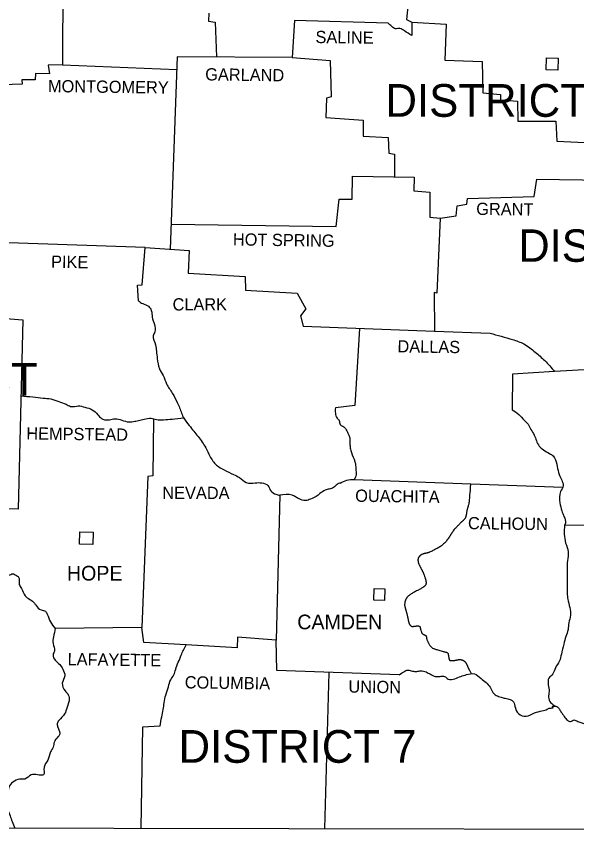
# Model space of a CAD drawing. Extents: x -819161 to 80911, y -6604 to 768454.
# Drawn here: x 80437.8 to 80589.5, y -4334.9 to -4115 of the extents above; entities that cross this region are included whole.
import ezdxf

# ---------------------------------------------------------------- set-up
doc = ezdxf.new("R2010")
doc.units = 0
doc.layers.add('SHET_Annotations', color=7, linetype='Continuous')

msp = doc.modelspace()

# ---------------------------------------------------------------- linework, layer by layer
at = {"layer": 'SHET_Annotations'}
for points in [[(80492.66, -4061.86), (80492.3, -4073.01), (80474.67, -4073.1), (80472.33, -4075.08), (80470.97, -4078.17), (80469.07, -4078.08), (80468.98, -4079.8), (80466.73, -4080.06), (80466.82, -4081.65), (80455.58, -4081.39), (80455.14, -4082.62), (80450.51, -4082.8), (80450.38, -4128.16), (80446.45, -4128.25), (80446.81, -4130.54), (80443.06, -4130.5), (80442.97, -4132.22), (80439.31, -4132.22), (80439.4, -4133.41), (80434.02, -4133.59), (80433.89, -4138.3), (80428.64, -4137.82), (80427.76, -4176)], [(80569.37, -4105.06), (80563.82, -4104.4), (80564.04, -4106.52), (80553.85, -4106.91), (80553.54, -4109.91), (80543.98, -4110.44), (80543.45, -4115.91), (80544.86, -4116.61), (80544.86, -4120.18)], [(80489.97, -4114.19), (80489.84, -4116.3), (80491.64, -4116.61), (80491.97, -4126.02)], [(80538.46, -4116.92), (80513.16, -4116.17), (80512.45, -4126.14), (80481.37, -4125.96), (80479.46, -4178.02)], [(80544.86, -4116.62), (80554.12, -4117.19), (80553.76, -4126.89), (80563.9, -4127.28), (80564.12, -4135.75), (80568.89, -4136.14), (80568.89, -4137.6), (80573.43, -4137.95), (80573.56, -4143.37), (80583.79, -4143.37), (80584.14, -4148.75), (80593.57, -4149.19), (80593.53, -4159.28)], [(80512.45, -4126.14), (80522.73, -4127.02), (80523.03, -4136.81), (80521.76, -4137.2), (80521.58, -4142.4), (80531.72, -4143.15), (80531.72, -4147.43), (80538.46, -4147.78), (80538.6, -4152.02), (80540.18, -4152.28), (80540.14, -4158.43)], [(80450.38, -4128.16), (80481.25, -4129.37)], [(80479.71, -4171.19), (80524.36, -4171.86), (80525.19, -4164.45), (80528.72, -4164.49), (80528.81, -4158.28), (80545.52, -4158.5), (80545.43, -4162.24), (80549.75, -4162.55), (80549.71, -4169.34), (80552.53, -4169.61)], [(80552.53, -4169.61), (80556.85, -4168.95), (80557.16, -4166.3), (80559.72, -4165.86), (80559.89, -4164.32), (80577.97, -4163.74), (80578.67, -4159.07), (80597.19, -4159.33)], [(80552.53, -4169.61), (80551.6, -4189.89), (80550.94, -4189.67), (80550.99, -4200.14)], [(80472.73, -4177.54), (80427.76, -4176), (80397.91, -4175.96), (80397.25, -4184.82), (80398.31, -4185.57), (80398.26, -4195.53), (80375.89, -4194.51)], [(80427.76, -4176), (80427.76, -4186.32), (80429.48, -4186.62), (80429.3, -4196.24), (80439.62, -4197.07), (80438.34, -4248.3), (80417.27, -4247.82)], [(80470.88, -4191.96), (80470.66, -4187.68), (80471.94, -4187.59), (80472.73, -4177.54), (80484.63, -4178.38), (80484.37, -4184.51), (80499.76, -4185.35), (80499.89, -4189.05), (80513.82, -4189.89), (80516.2, -4194.08), (80514.75, -4195.97), (80515.45, -4198.84), (80550.99, -4200.14)], [(80530.72, -4199.4), (80529.47, -4220.26), (80524.18, -4220.88)], [(80550.99, -4200.14), (80566.02, -4200.69)], [(80583.48, -4211.07), (80572.1, -4211.76), (80572.02, -4221.45)], [(80594.77, -4210.39), (80583.48, -4211.07)], [(80474.98, -4223.84), (80474.8, -4239.22), (80473.39, -4239.4), (80471.85, -4280.27)], [(80529.28, -4240.21), (80560.86, -4241.38), (80585.73, -4242.35)], [(80509.15, -4244.51), (80508.13, -4283.66), (80497.68, -4282.91), (80497.59, -4285.78), (80483.81, -4284.98)], [(80586.17, -4252.58), (80621.26, -4252.49)], [(80416.6, -4271.67), (80416.78, -4334.45), (80701.11, -4334.94)], [(80483.81, -4284.98), (80472.38, -4284.32), (80471.85, -4280.27), (80448.35, -4280.49)], [(80541.42, -4293.1), (80508.35, -4291.86), (80508.13, -4283.66)], [(80522.42, -4292.39), (80521.24, -4334.63)], [(80476.79, -4306.9), (80472.02, -4307.21), (80471.51, -4334.55)]]:
    msp.add_lwpolyline(points, dxfattribs=at)
for points in [[(80581.23, -4129.49), (80581.32, -4126.27), (80584.45, -4126.36), (80584.36, -4129.57)], [(80454.96, -4257.74), (80455.05, -4254.43), (80458.62, -4254.52), (80458.53, -4257.83)], [(80534.58, -4272.91), (80534.67, -4269.69), (80537.54, -4269.78), (80537.45, -4272.99)]]:
    msp.add_lwpolyline(points, close=True, dxfattribs=at)
for points in [[(80544.86, -4120.18), (80542.87, -4118.99), (80541.64, -4118.33), (80540.45, -4118.38), (80539.43, -4117.76), (80538.46, -4116.92)], [(80470.88, -4191.96), (80472.07, -4192.71), (80473.57, -4193.41), (80474.36, -4194.56), (80474.62, -4196.37), (80475.2, -4198.31), (80475.33, -4200.29), (80474.89, -4201.39), (80475.51, -4203.86), (80475.73, -4205.58), (80475.99, -4207.57), (80476.56, -4210.3), (80477.58, -4212.15), (80478.5, -4214.4), (80480.05, -4216.87), (80481.41, -4219.47), (80482.03, -4220.84), (80483.18, -4223.7), (80484.63, -4225.69), (80487.01, -4228.64), (80489.09, -4231.68), (80490.23, -4233.93), (80492.04, -4236.4), (80494.07, -4237.63), (80496.62, -4238.91), (80498.26, -4239.75), (80500.06, -4241.07), (80502.49, -4241.16), (80504.25, -4241.16), (80505.93, -4241.91), (80506.68, -4243.28), (80508.09, -4244.25), (80509.15, -4244.51)], [(80566.02, -4200.69), (80572.1, -4202.41), (80575.19, -4203.6), (80578.28, -4205.85), (80580.83, -4208.1), (80583.48, -4211.07)], [(80439.1, -4217.67), (80442.35, -4217.93), (80445.09, -4218.24), (80447.16, -4218.46), (80449.32, -4219.21), (80451.3, -4219.91), (80452.54, -4220.48), (80454.61, -4220.35), (80456.42, -4220.7), (80458.4, -4221.41), (80459.9, -4222.73), (80460.87, -4223.75), (80462.63, -4224.14), (80464.13, -4223.88), (80465.9, -4224.06), (80467.88, -4224.63), (80469.55, -4224.58), (80470.88, -4224.28), (80472.42, -4223.92), (80474.32, -4223.7), (80475.77, -4224.06), (80477.71, -4224.1), (80480, -4223.92), (80483.11, -4223.58)], [(80524.18, -4220.88), (80524.18, -4222.34), (80524.66, -4223.7), (80525.19, -4224.32), (80525.46, -4225.38), (80526.16, -4225.82), (80527.13, -4226.79), (80527.71, -4228.07), (80528.06, -4228.95), (80528.1, -4230.05), (80528.15, -4231.11), (80528.32, -4232.39), (80529.25, -4234.77), (80529.51, -4235.69), (80529.65, -4236.49), (80529.74, -4237.81), (80529.69, -4239.35), (80529.28, -4240.21)], [(80572.02, -4221.45), (80573.78, -4222.64), (80575.23, -4224.23), (80576.34, -4225.33), (80577.09, -4226.7), (80577.97, -4228.24), (80579.33, -4231.2), (80580.48, -4232.21), (80582.11, -4233.23), (80583.08, -4233.89), (80584.1, -4236.14), (80584.58, -4238.38), (80585.42, -4240.41), (80585.82, -4241.96), (80585.11, -4243.5), (80584.93, -4246.58), (80585.46, -4248.75), (80586.04, -4250.24), (80586.43, -4252.05), (80586.17, -4252.58)], [(80525.46, -4241.2), (80524.66, -4241.56), (80523.69, -4242.4), (80522.5, -4242.84), (80521.45, -4243.15), (80519.99, -4244.07), (80518.98, -4244.87), (80517.48, -4245.53), (80516.07, -4245.97), (80514.35, -4245.48), (80513.42, -4244.95), (80512.45, -4244.51), (80509.15, -4244.51)], [(80525.46, -4241.2), (80527.27, -4240.46), (80529.28, -4240.21)], [(80586.17, -4252.58), (80586.48, -4257.43), (80587.18, -4259.77), (80587.01, -4262.19), (80586.87, -4264.62), (80586.92, -4266.78), (80586.87, -4268.89), (80586.92, -4271.05), (80587.05, -4272.6), (80587.62, -4274.85), (80587.8, -4276.96), (80587.36, -4278.99), (80587.14, -4280.84), (80586.52, -4282.69), (80585.99, -4284.77), (80585.33, -4287.5), (80584.8, -4289.31), (80583.7, -4291.16), (80582.99, -4292.83), (80581.94, -4293.94), (80581.8, -4295.79), (80582.02, -4297.55), (80581.85, -4299.09), (80582.42, -4300.55), (80583.79, -4301.56)], [(80416.6, -4271.67), (80419.29, -4270.52), (80420.53, -4270.88), (80421.5, -4271.89), (80422.69, -4271.94), (80423.31, -4271.01), (80424.45, -4270.88), (80425.38, -4270.97), (80426.39, -4270.39), (80427.23, -4270), (80428.38, -4269.6), (80429.26, -4269.25), (80430.01, -4268.41), (80431.46, -4267.75), (80433.05, -4267.17), (80433.49, -4266.38), (80434.28, -4266.07), (80435.83, -4266.16), (80436.89, -4265.72), (80437.72, -4266.12), (80438.47, -4266.64), (80438.65, -4268.63), (80439.27, -4269.73), (80440.24, -4271.67), (80441.51, -4272.69), (80442.75, -4273.7), (80443.19, -4274.32), (80444.56, -4275.51), (80445.7, -4275.86), (80446.23, -4276.7), (80447.07, -4278.77), (80448.35, -4280.49)], [(80448.35, -4280.49), (80447.91, -4282.78), (80447.78, -4284.59), (80448.17, -4286.62), (80447.78, -4287.68), (80448.39, -4289.13), (80449.58, -4290.28), (80450.42, -4291.51), (80450.95, -4293.36), (80450.29, -4295.35), (80451.04, -4297.42), (80451.74, -4298.21), (80452.18, -4299.49), (80451.57, -4301.83), (80450.91, -4303.63), (80449.36, -4305.4), (80448.92, -4306.28), (80449.14, -4307.43), (80449.54, -4309.28), (80449.1, -4309.85), (80448.13, -4311.17), (80447.78, -4312.63), (80447.07, -4313.91), (80446.36, -4316.11), (80445.35, -4318.01), (80445.17, -4320.12), (80443.59, -4320.08), (80441.87, -4320.12), (80440.19, -4321.23), (80438.74, -4321.31), (80436.93, -4322.06), (80435.83, -4323.52), (80435.47, -4325.15), (80434.99, -4326.69), (80435.43, -4329.34), (80436.14, -4331.19), (80436.71, -4332.69), (80437.45, -4334.49)], [(80476.79, -4306.9), (80477.18, -4304.43), (80477.58, -4302.44), (80477.84, -4300.64), (80478.28, -4298.52), (80478.99, -4296.27), (80479.61, -4294.42), (80480.44, -4293.1), (80480.97, -4291.55), (80481.68, -4289.66), (80482.43, -4287.76), (80483.81, -4284.98)], [(80541.42, -4293.1), (80542.7, -4292.22), (80543.84, -4291.78), (80545.03, -4292.04), (80546.22, -4292.13), (80547.33, -4292), (80548.74, -4292.26), (80549.88, -4292.92), (80551.21, -4293.49), (80552.53, -4293.49), (80553.67, -4293.49), (80554.73, -4294.2), (80556.54, -4294.11), (80558.13, -4293.49), (80559.67, -4293.01), (80561.79, -4292.79), (80563.59, -4294.07), (80564.96, -4295.17), (80566.02, -4296.4), (80566.81, -4297.82), (80567.7, -4298.61), (80569.06, -4299.14), (80570.16, -4299.4), (80571.44, -4299.76), (80572.15, -4300.11), (80572.77, -4301.52), (80573.78, -4303.59), (80575.76, -4304.25), (80578.1, -4303.33), (80580.08, -4302.8), (80581.49, -4302.36), (80582.29, -4302.05), (80583.08, -4301.92), (80582.91, -4301.78), (80583.79, -4301.56), (80584.67, -4302.18), (80585.2, -4303.02), (80586.12, -4304.3), (80586.96, -4305.35), (80587.8, -4305.71), (80588.73, -4305.27), (80589.83, -4305.66), (80590.84, -4306.02), (80592.03, -4306.37), (80593, -4306.41), (80594.37, -4306.72), (80595.34, -4307.29), (80596.26, -4307.87), (80597.23, -4308.84), (80598.16, -4310.42), (80598.47, -4311.66), (80599.53, -4312.89), (80600.58, -4312.89), (80602, -4314.88), (80602.57, -4315.67), (80603.72, -4317.04), (80604.55, -4317.08), (80606.22, -4317.35)]]:
    msp.add_spline(points, degree=3, dxfattribs=at)
msp.add_open_spline([(80560.76, -4241.38), (80560.63, -4242.97), (80560.5, -4244.56), (80560.38, -4246.14), (80560.34, -4246.55), (80560.25, -4246.95), (80560.14, -4247.34), (80560.08, -4247.54), (80560.02, -4247.73), (80559.96, -4247.93), (80559.91, -4248.13), (80559.85, -4248.33), (80559.8, -4248.52), (80559.71, -4248.89), (80559.69, -4249.27), (80559.62, -4249.65), (80559.58, -4249.83), (80559.54, -4250.02), (80559.49, -4250.2), (80559.47, -4250.29), (80559.44, -4250.38), (80559.4, -4250.47), (80559.38, -4250.51), (80559.36, -4250.56), (80559.34, -4250.6), (80559.32, -4250.64), (80559.3, -4250.69), (80559.27, -4250.73), (80559.2, -4250.86), (80559.12, -4250.97), (80559.02, -4251.08), (80558.93, -4251.19), (80558.83, -4251.29), (80558.72, -4251.39), (80558.61, -4251.48), (80558.5, -4251.57), (80558.4, -4251.67), (80558.29, -4251.77), (80558.18, -4251.86), (80558.08, -4251.96), (80557.88, -4252.18), (80557.67, -4252.39), (80557.47, -4252.6), (80557.26, -4252.82), (80557.06, -4253.03), (80556.85, -4253.24), (80556.44, -4253.66), (80556.09, -4254.13), (80555.75, -4254.61), (80555.65, -4254.74), (80555.56, -4254.88), (80555.47, -4255.02), (80555.39, -4255.16), (80555.3, -4255.3), (80555.22, -4255.45), (80555.13, -4255.59), (80555.05, -4255.73), (80554.96, -4255.87), (80554.88, -4256.01), (80554.79, -4256.15), (80554.69, -4256.28), (80554.39, -4256.7), (80554.04, -4257.07), (80553.67, -4257.43), (80553.28, -4257.82), (80552.87, -4258.2), (80552.4, -4258.49), (80551.95, -4258.76), (80551.49, -4259), (80551.03, -4259.24), (80550.56, -4259.48), (80550.1, -4259.72), (80549.62, -4259.94), (80549.49, -4260), (80549.35, -4260.05), (80549.21, -4260.09), (80549.07, -4260.12), (80548.93, -4260.15), (80548.79, -4260.18), (80548.65, -4260.21), (80548.51, -4260.24), (80548.36, -4260.26), (80548.22, -4260.29), (80548.08, -4260.34), (80547.94, -4260.38), (80547.72, -4260.46), (80547.51, -4260.56), (80547.31, -4260.69), (80547.21, -4260.75), (80547.12, -4260.82), (80547.04, -4260.9), (80546.99, -4260.94), (80546.95, -4260.99), (80546.91, -4261.03), (80546.87, -4261.08), (80546.83, -4261.13), (80546.8, -4261.18), (80546.7, -4261.32), (80546.64, -4261.47), (80546.59, -4261.63), (80546.54, -4261.79), (80546.52, -4261.96), (80546.53, -4262.12), (80546.56, -4262.44), (80546.62, -4262.77), (80546.75, -4263.07), (80546.85, -4263.3), (80546.95, -4263.51), (80547.06, -4263.72), (80547.17, -4263.94), (80547.29, -4264.15), (80547.4, -4264.37), (80547.51, -4264.58), (80547.62, -4264.8), (80547.73, -4265.01), (80547.85, -4265.23), (80547.94, -4265.45), (80548.03, -4265.67), (80548.19, -4266.08), (80548.34, -4266.49), (80548.47, -4266.91), (80548.51, -4267.04), (80548.55, -4267.16), (80548.59, -4267.29), (80548.62, -4267.42), (80548.65, -4267.55), (80548.68, -4267.68), (80548.7, -4267.81), (80548.71, -4267.94), (80548.72, -4268.07), (80548.72, -4268.13), (80548.72, -4268.2), (80548.72, -4268.26), (80548.71, -4268.33), (80548.71, -4268.39), (80548.69, -4268.45), (80548.66, -4268.62), (80548.58, -4268.78), (80548.47, -4268.92), (80548.36, -4269.07), (80548.23, -4269.19), (80548.08, -4269.29), (80547.68, -4269.54), (80547.29, -4269.77), (80546.89, -4270), (80546.39, -4270.27), (80545.88, -4270.52), (80545.39, -4270.79), (80544.94, -4271.04), (80544.52, -4271.32), (80544.11, -4271.63), (80543.89, -4271.79), (80543.7, -4271.98), (80543.54, -4272.2), (80543.45, -4272.3), (80543.38, -4272.41), (80543.32, -4272.53), (80543.25, -4272.65), (80543.19, -4272.77), (80543.14, -4272.91), (80543.02, -4273.2), (80542.95, -4273.5), (80542.93, -4273.81), (80542.91, -4274.11), (80542.93, -4274.42), (80543.01, -4274.71), (80543.05, -4274.89), (80543.09, -4275.06), (80543.14, -4275.23), (80543.19, -4275.4), (80543.24, -4275.58), (80543.29, -4275.75), (80543.34, -4275.92), (80543.39, -4276.09), (80543.44, -4276.27), (80543.49, -4276.44), (80543.54, -4276.61), (80543.58, -4276.79), (80543.68, -4277.21), (80543.75, -4277.64), (80543.84, -4278.06), (80543.88, -4278.25), (80543.93, -4278.43), (80543.97, -4278.61), (80544.02, -4278.79), (80544.08, -4278.97), (80544.14, -4279.15), (80544.21, -4279.32), (80544.3, -4279.48), (80544.42, -4279.62), (80544.48, -4279.69), (80544.54, -4279.76), (80544.62, -4279.81), (80544.65, -4279.84), (80544.69, -4279.87), (80544.73, -4279.89), (80544.77, -4279.92), (80544.81, -4279.94), (80544.86, -4279.96), (80544.92, -4279.99), (80544.98, -4280), (80545.04, -4280), (80545.11, -4280), (80545.17, -4279.99), (80545.23, -4279.98), (80545.3, -4279.97), (80545.36, -4279.95), (80545.42, -4279.94), (80545.48, -4279.93), (80545.54, -4279.92), (80545.61, -4279.92), (80545.67, -4279.91), (80545.72, -4279.91), (80545.78, -4279.9), (80545.84, -4279.9), (80545.9, -4279.89), (80545.96, -4279.88), (80546.08, -4279.86), (80546.19, -4279.84), (80546.31, -4279.82), (80546.43, -4279.8), (80546.55, -4279.8), (80546.67, -4279.83), (80546.73, -4279.84), (80546.78, -4279.86), (80546.84, -4279.89), (80546.87, -4279.9), (80546.9, -4279.92), (80546.93, -4279.94), (80546.96, -4279.96), (80546.99, -4279.98), (80547.02, -4280), (80547.07, -4280.06), (80547.11, -4280.12), (80547.12, -4280.19), (80547.14, -4280.26), (80547.13, -4280.33), (80547.15, -4280.4), (80547.18, -4280.52), (80547.21, -4280.64), (80547.24, -4280.75), (80547.33, -4281.1), (80547.44, -4281.43), (80547.59, -4281.77), (80547.64, -4281.87), (80547.72, -4281.97), (80547.82, -4282.02), (80547.93, -4282.08), (80548.05, -4282.13), (80548.16, -4282.19), (80548.28, -4282.24), (80548.39, -4282.3), (80548.5, -4282.35), (80548.61, -4282.4), (80548.69, -4282.5), (80548.74, -4282.6), (80548.77, -4282.67), (80548.79, -4282.73), (80548.8, -4282.8), (80548.81, -4282.86), (80548.82, -4282.93), (80548.83, -4283), (80548.84, -4283.07), (80548.85, -4283.14), (80548.86, -4283.2), (80548.87, -4283.27), (80548.89, -4283.33), (80548.91, -4283.4), (80549, -4283.66), (80549.11, -4283.91), (80549.22, -4284.16), (80549.33, -4284.42), (80549.46, -4284.66), (80549.62, -4284.9), (80549.9, -4285.32), (80550.26, -4285.72), (80550.72, -4285.91), (80551.01, -4286.03), (80551.3, -4286.13), (80551.6, -4286.22), (80552.19, -4286.4), (80552.78, -4286.58), (80553.37, -4286.75), (80553.67, -4286.84), (80553.98, -4286.89), (80554.29, -4286.97), (80554.34, -4286.98), (80554.38, -4287), (80554.43, -4287.03), (80554.56, -4287.13), (80554.65, -4287.26), (80554.68, -4287.41), (80554.73, -4287.65), (80554.77, -4287.9), (80554.81, -4288.15), (80554.86, -4288.39), (80554.91, -4288.63), (80554.95, -4288.87), (80554.97, -4288.96), (80555.02, -4289.04), (80555.1, -4289.11), (80555.18, -4289.18), (80555.26, -4289.21), (80555.35, -4289.22), (80555.56, -4289.23), (80555.76, -4289.23), (80555.97, -4289.21), (80556.17, -4289.19), (80556.38, -4289.17), (80556.58, -4289.13), (80556.73, -4289.1), (80556.88, -4289.07), (80557.03, -4289.04), (80557.17, -4289.01), (80557.32, -4288.98), (80557.47, -4288.95), (80557.73, -4288.91), (80558, -4288.93), (80558.27, -4288.98), (80558.4, -4289.01), (80558.54, -4289.05), (80558.66, -4289.11), (80558.73, -4289.15), (80558.8, -4289.18), (80558.86, -4289.22), (80558.93, -4289.26), (80558.99, -4289.3), (80559.05, -4289.35), (80559.21, -4289.48), (80559.35, -4289.62), (80559.45, -4289.79), (80559.54, -4289.95), (80559.63, -4290.11), (80559.72, -4290.28), (80559.78, -4290.41), (80559.85, -4290.54), (80559.91, -4290.67), (80559.97, -4290.8), (80560.03, -4290.94), (80560.09, -4291.07), (80560.15, -4291.2), (80560.2, -4291.34), (80560.26, -4291.47), (80560.32, -4291.6), (80560.4, -4291.73), (80560.46, -4291.86), (80560.61, -4292.14), (80560.74, -4292.44), (80560.95, -4292.68)], degree=3, dxfattribs=at)

# ---------------------------------------------------------------- texts
for s, rotation, p in [('SALINE', 359.1885, (80518.78, -4122.25)), ('GARLAND', 359.2717, (80488.94, -4132.35)), ('MONTGOMERY', 359.2707, (80446.39, -4135.52)), ('GRANT', 359.3139, (80562.28, -4168.72)), ('HOT SPRING', 359.1956, (80496.43, -4176.97)), ('PIKE', 359.1737, (80447.23, -4183.01)), ('DALLAS', 359.2802, (80540.96, -4205.89)), ('HEMPSTEAD', 359.2571, (80440.53, -4229.43)), ('OUACHITA', 359.2027, (80529.52, -4246.27)), ('CALHOUN', 359.2686, (80560.04, -4253.68)), ('LAFAYETTE', 359.2511, (80451.7, -4290.45)), ('COLUMBIA', 359.2105, (80483.4, -4296.71)), ('UNION', 359.2015, (80527.68, -4297.86))]:
    msp.add_text(s, height=3.307, rotation=rotation, dxfattribs=at).set_placement(p)
for s, height, p in [('DISTRICT 6', 8.845, (80537.72, -4142.2)), ('DISTRICT 2', 8.767, (80573.7, -4181.4)), ('CLARK', 3.307, (80480.12, -4194.56)), ('DISTRICT', 8.845, (80389.09, -4217.61)), ('NEVADA', 3.307, (80477.35, -4245.53)), ('HOPE', 3.968, (80451.53, -4267.57)), ('CAMDEN', 3.968, (80513.87, -4280.75)), ('DISTRICT 7', 8.845, (80481.73, -4316.84))]:
    msp.add_text(s, height=height, dxfattribs=at).set_placement(p)

doc.saveas('drawing.dxf')
